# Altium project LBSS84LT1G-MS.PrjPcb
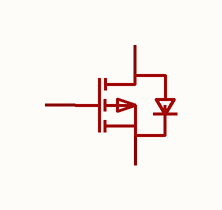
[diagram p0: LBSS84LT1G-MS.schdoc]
1 sheet, 1 parts. Net scope: global (net labels, ports and power ports of the same name join across sheets).

## Sheet LBSS84LT1G-MS.schdoc
size 127 x 101 mm

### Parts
Q?  lbss84lt1g-ms  [SOT-23-3_L3.0-W1.7-P0.95-LS2.9-BR]  (value not drawn)

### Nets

Not connected (* = marked no-connect by the designer): Q? 1(G) 2(S) 3(D)

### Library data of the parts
Q? = lbss84lt1g-ms: 数量:1个P沟道;漏源电压(Vdss):55V;连续漏极电流(Id):300mA;导通电阻(RDS(on)):4Ω@10V;耗散功率(Pd):1W;阈值电压(Vgs(th)):1.7V;; Manufacturer: MSKSEMI(美森科); AddInBom: yes; ModelId: 89cb27a44ab2466697082bb9fd73a7d0; ModelName: SOT-23-3L_L2.9-W1.6-H1.1-LS2.8-P0.95; ModelTransform: 114.173,110.236,0,90,0,0,0,0,0; Number: 1个P沟道; Drain to Source Voltage: 55V; Current - Continuous Drain(Id): 300mA; RDS(on): 4Ω@10V; Pd - Power Dissipation: 1W; Gate Threshold Voltage (Vgs(th)): 1.7V; Gate Charge(Qg): 2.8nC@10V; Input Capacitance(Ciss): 30.5pF; Reverse Transfer Capacitance (Crss@Vds): 7pF; Output Capacitance(Coss): 15.1pF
